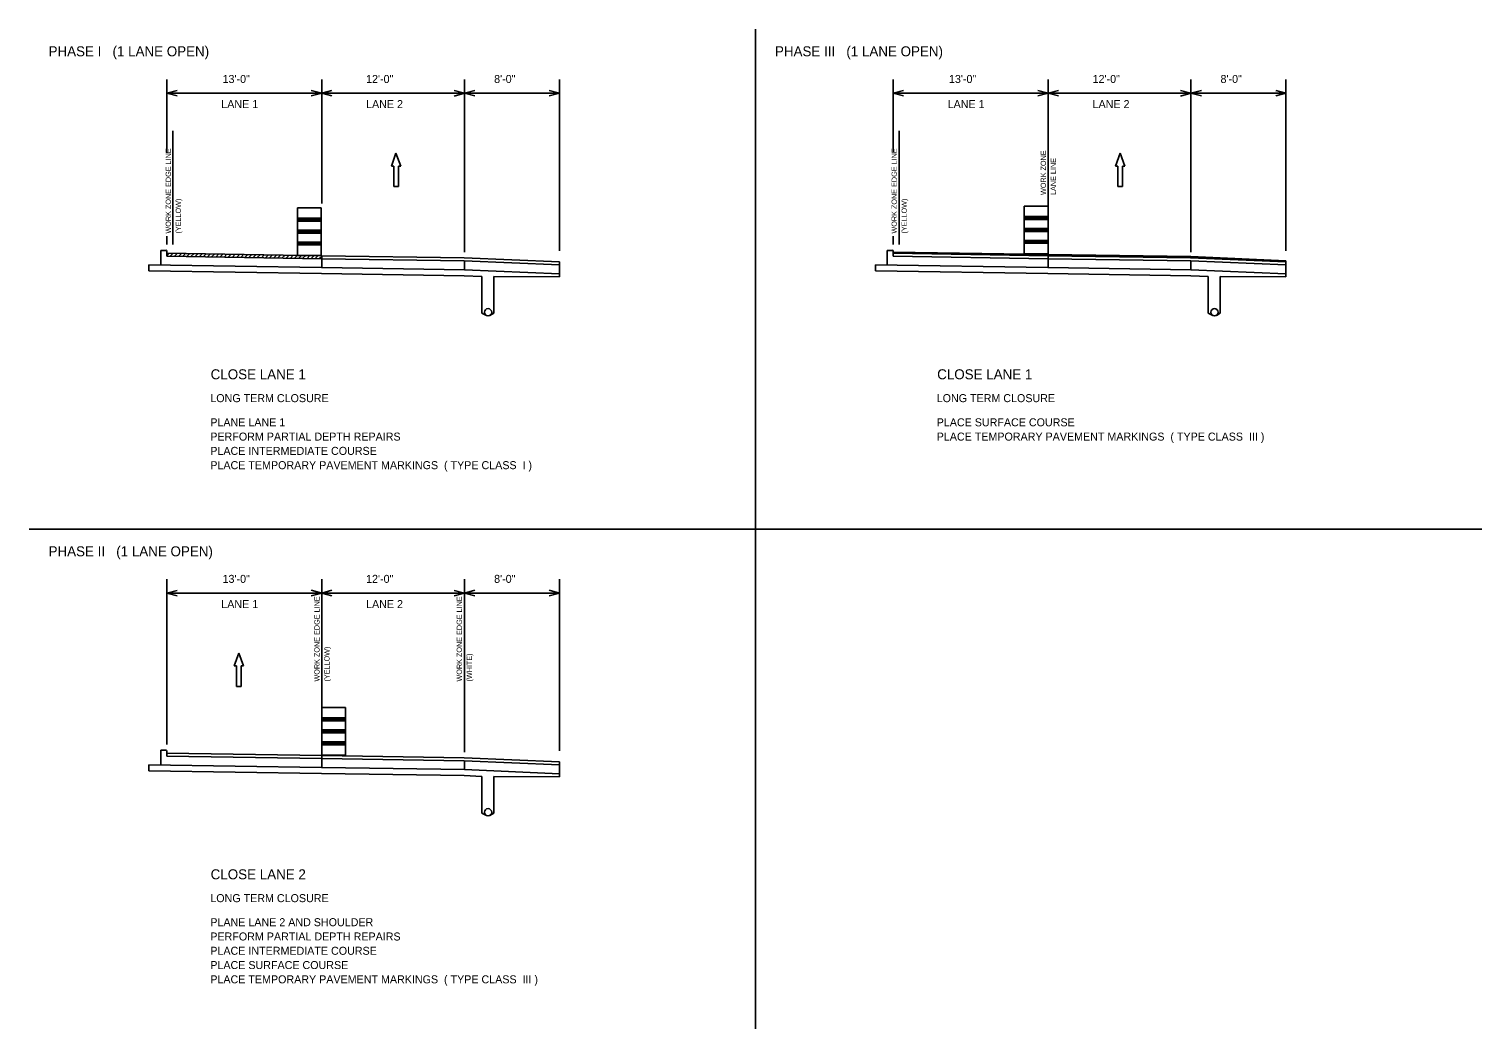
# Model space of a CAD drawing. Extents: x -161 to 291, y -369 to 173.
# Drawn here: x 169.5 to 291.5, y 2 to 86 of the extents above; entities that cross this region are included whole.
import ezdxf

# ---------------------------------------------------------------- set-up
doc = ezdxf.new("R2010")
doc.units = 0
for name, color, linetype in [('Level 1', 7, 'Continuous'), ('Level 11', 7, 'Continuous'), ('Level 21', 7, 'Continuous'), ('Level 25', 7, 'Continuous'), ('Level 26', 7, 'Continuous'), ('Level 6', 7, 'Continuous'), ('Level 7', 7, 'Continuous')]:
    doc.layers.add(name, color=color, linetype=linetype)

msp = doc.modelspace()

# ---------------------------------------------------------------- linework, layer by layer
at = {"layer": 'Level 1'}
for p, q in [((230.49, 44), (230.49, 86)), ((230.49, 44), (230.49, 86)), ((169.49, 44), (230.49, 44)), ((169.49, 44), (230.49, 44)), ((230.49, 2.01), (230.49, 44)), ((230.49, 44), (291.48, 44))]:
    msp.add_line(p, q, dxfattribs=at)
at = {"layer": 'Level 11'}
for p, q in [((180.56, 66.17), (180.56, 67.41)), ((180.56, 67.41), (180.97, 67.41)), ((181.06, 66.91), (181.06, 67.33)), ((194.06, 66.96), (181.06, 67.16)), ((181.06, 66.98), (181.24, 67.16)), ((181.34, 66.91), (181.58, 67.16)), ((181.69, 66.91), (181.93, 67.15)), ((182.03, 66.9), (182.28, 67.15)), ((182.38, 66.89), (182.63, 67.14)), ((182.73, 66.89), (182.98, 67.14)), ((183.08, 66.88), (183.33, 67.13)), ((183.43, 66.88), (183.67, 67.12)), ((183.78, 66.87), (184.02, 67.12)), ((184.12, 66.87), (184.37, 67.11)), ((184.47, 66.86), (184.72, 67.11)), ((184.82, 66.86), (185.07, 67.1)), ((185.17, 66.85), (185.41, 67.1)), ((241.55, 66.17), (241.55, 67.41)), ((241.55, 67.41), (241.97, 67.41)), ((242.05, 66.91), (242.05, 67.33)), ((194.04, 65.97), (179.56, 66.19)), ((179.56, 65.69), (179.56, 66.19)), ((194.06, 66.71), (181.06, 66.91)), ((185.52, 66.85), (185.76, 67.09)), ((185.86, 66.84), (186.11, 67.09)), ((186.21, 66.84), (186.46, 67.08)), ((186.56, 66.83), (186.81, 67.08)), ((186.91, 66.82), (187.16, 67.07)), ((187.26, 66.82), (187.5, 67.07)), ((187.61, 66.81), (187.85, 67.06)), ((187.95, 66.81), (188.2, 67.05)), ((188.3, 66.8), (188.55, 67.05)), ((188.65, 66.8), (188.9, 67.04)), ((189, 66.79), (189.24, 67.04)), ((189.35, 66.79), (189.59, 67.03)), ((189.69, 66.78), (189.94, 67.03)), ((190.04, 66.78), (190.29, 67.02)), ((190.39, 66.77), (190.64, 67.02)), ((190.74, 66.77), (190.99, 67.01)), ((191.09, 66.76), (191.33, 67.01)), ((191.44, 66.75), (191.68, 67)), ((191.78, 66.75), (192.03, 67)), ((192.13, 66.74), (192.38, 66.99)), ((192.48, 66.74), (192.73, 66.98)), ((192.83, 66.73), (193.07, 66.98)), ((193.18, 66.73), (193.42, 66.97)), ((193.52, 66.72), (193.77, 66.97)), ((193.87, 66.72), (194.06, 66.9)), ((194.06, 66.71), (194.06, 66.96)), ((206.03, 66.78), (194.06, 66.96)), ((206.03, 66.53), (194.06, 66.71)), ((194.06, 65.97), (194.06, 66.71)), ((206.05, 65.78), (194.06, 65.97)), ((214.03, 66.44), (206.03, 66.78)), ((214.03, 66.19), (206.03, 66.53)), ((206.06, 65.78), (206.06, 66.53)), ((214.03, 65.2), (214.03, 66.44)), ((255.04, 65.97), (240.55, 66.19)), ((240.55, 65.69), (240.55, 66.19)), ((255.05, 66.96), (255.05, 66.71)), ((255.05, 65.97), (255.05, 66.71)), ((267.04, 65.78), (255.05, 65.97)), ((267.05, 65.78), (267.05, 66.53)), ((275.02, 65.2), (275.02, 66.19)), ((194.04, 65.47), (179.56, 65.69)), ((206.03, 65.28), (194.04, 65.47)), ((207.5, 65.22), (206.03, 65.28)), ((214.03, 65.45), (206.05, 65.78)), ((207.51, 65.22), (207.51, 62.13)), ((208.51, 65.22), (208.51, 62.14)), ((214.03, 65.2), (208.51, 65.22)), ((255.03, 65.47), (240.55, 65.69)), ((267.03, 65.28), (255.04, 65.47)), ((268.5, 65.22), (267.03, 65.28)), ((275.02, 65.45), (267.04, 65.78)), ((268.5, 65.22), (268.5, 62.13)), ((269.5, 65.22), (269.5, 62.14)), ((275.02, 65.2), (269.5, 65.22)), ((207.9, 61.94), (207.51, 62.13)), ((208.19, 61.95), (208.51, 62.14)), ((268.89, 61.94), (268.5, 62.13)), ((269.18, 61.95), (269.5, 62.14)), ((180.56, 24.18), (180.56, 25.42)), ((180.56, 25.42), (180.97, 25.42)), ((181.06, 24.92), (181.06, 25.34)), ((206.03, 24.78), (194.06, 24.97)), ((194.06, 24.97), (194.06, 24.72)), ((194.06, 23.97), (194.06, 24.72)), ((194.06, 24.72), (206.03, 24.53)), ((214.03, 24.45), (206.03, 24.78)), ((206.03, 24.53), (214.03, 24.2)), ((206.06, 23.78), (206.06, 24.53)), ((214.03, 24.2), (214.03, 24.45)), ((194.04, 23.97), (179.56, 24.19)), ((179.56, 23.69), (179.56, 24.19)), ((194.04, 23.47), (179.56, 23.69)), ((206.03, 23.29), (194.04, 23.47)), ((206.05, 23.79), (194.06, 23.97)), ((207.5, 23.22), (206.03, 23.29)), ((214.03, 23.45), (206.05, 23.79)), ((207.51, 23.22), (207.51, 20.13)), ((208.51, 23.22), (208.51, 20.14)), ((214.03, 23.2), (208.51, 23.22)), ((214.03, 23.2), (214.03, 24.2)), ((207.9, 19.94), (207.51, 20.13)), ((208.19, 19.95), (208.51, 20.14))]:
    msp.add_line(p, q, dxfattribs=at)
for centre in [(208.03, 62.21), (269.02, 62.21), (208.03, 20.21)]:
    msp.add_circle(centre, 0.304, dxfattribs=at)
for centre in [(180.97, 67.33), (241.97, 67.33), (180.97, 25.34)]:
    msp.add_arc(centre, 0.083, 0, 90, dxfattribs=at)
at = {"layer": 'Level 21'}
for p, q in [((242.05, 67.26), (242.05, 66.91)), ((255.05, 67.06), (242.05, 67.26)), ((255.05, 66.96), (242.05, 67.16)), ((255.05, 66.71), (242.05, 66.91)), ((255.05, 66.71), (255.05, 66.96)), ((267.02, 66.78), (255.05, 66.96)), ((255.05, 66.71), (267.03, 66.53)), ((267.03, 66.88), (255.06, 67.06)), ((275.02, 66.44), (267.02, 66.78)), ((275.02, 66.54), (267.03, 66.88)), ((267.03, 66.53), (275.02, 66.19)), ((275.02, 66.19), (275.02, 66.54)), ((194.06, 24.97), (181.06, 25.17)), ((181.06, 25.17), (181.06, 24.92)), ((194.06, 24.72), (181.06, 24.92)), ((194.06, 24.72), (194.06, 24.97))]:
    msp.add_line(p, q, dxfattribs=at)
at = {"layer": 'Level 25'}
for p, q in [((192.03, 70.98), (192.03, 66.98)), ((192.03, 70.98), (194.03, 70.98)), ((194.03, 70.98), (194.03, 66.98)), ((253.05, 71.12), (253.05, 67.12)), ((253.05, 71.12), (255.05, 71.12)), ((255.05, 71.12), (255.05, 67.12)), ((192.03, 70.11), (194.03, 70.11)), ((192.03, 69.98), (194.03, 69.98)), ((192.03, 69.86), (194.03, 69.86)), ((253.05, 70.25), (255.05, 70.25)), ((253.05, 70.12), (255.05, 70.12)), ((253.05, 70), (255.05, 70)), ((192.03, 69.11), (194.03, 69.11)), ((192.03, 68.98), (194.03, 68.98)), ((192.03, 68.86), (194.03, 68.86)), ((253.05, 69.25), (255.05, 69.25)), ((253.05, 69.12), (255.05, 69.12)), ((253.05, 69), (255.05, 69)), ((192.03, 68.11), (194.03, 68.11)), ((192.03, 67.98), (194.03, 67.98)), ((192.03, 67.86), (194.03, 67.86)), ((253.05, 68.25), (255.05, 68.25)), ((253.05, 68.12), (255.05, 68.12)), ((253.05, 68), (255.05, 68)), ((253.05, 67.12), (255.05, 67.12)), ((192.03, 66.98), (194.03, 66.98)), ((194.06, 29.01), (194.06, 25.01)), ((194.06, 29.01), (196.06, 29.01)), ((194.06, 28.13), (196.06, 28.13)), ((196.06, 29.01), (196.06, 25.01)), ((194.06, 28.01), (196.06, 28.01)), ((194.06, 27.88), (196.06, 27.88)), ((194.06, 27.13), (196.06, 27.13)), ((194.06, 27.01), (196.06, 27.01)), ((194.06, 26.88), (196.06, 26.88)), ((194.06, 26.13), (196.06, 26.13)), ((194.06, 26.01), (196.06, 26.01)), ((194.06, 25.88), (196.06, 25.88)), ((194.06, 25.01), (196.06, 25.01))]:
    msp.add_line(p, q, dxfattribs=at)
at = {"layer": 'Level 26'}
for p, q in [((181.06, 75.61), (181.06, 81.77)), ((194.06, 71.35), (194.06, 81.77)), ((206.06, 67.26), (206.06, 81.77)), ((214.03, 67.36), (214.03, 81.77)), ((242.05, 75.62), (242.05, 81.77)), ((255.05, 67.13), (255.05, 81.77)), ((267.05, 67.26), (267.05, 81.77)), ((275.02, 67.36), (275.02, 81.77)), ((181.06, 80.61), (194.06, 80.61)), ((206.06, 80.61), (194.06, 80.61)), ((214.03, 80.61), (206.06, 80.61)), ((242.05, 80.61), (255.05, 80.61)), ((267.05, 80.61), (255.05, 80.61)), ((275.02, 80.61), (267.05, 80.61)), ((181.56, 67.89), (181.56, 77.45)), ((242.55, 67.89), (242.55, 77.45)), ((181.06, 67.89), (181.06, 68.61)), ((242.05, 67.89), (242.05, 68.61)), ((181.06, 26.61), (181.06, 39.78)), ((194.06, 25.13), (194.06, 39.78)), ((206.06, 25.26), (206.06, 39.78)), ((214.03, 25.37), (214.03, 39.78)), ((181.06, 38.62), (194.06, 38.62)), ((206.06, 38.62), (194.06, 38.62)), ((214.03, 38.62), (206.06, 38.62)), ((181.06, 25.9), (181.06, 26.61))]:
    msp.add_line(p, q, dxfattribs=at)
for points in [[(181.92, 80.38), (181.06, 80.61), (181.92, 80.85)], [(193.19, 80.85), (194.06, 80.61), (193.19, 80.38)], [(194.92, 80.85), (194.06, 80.61), (194.92, 80.38)], [(205.19, 80.37), (206.06, 80.61), (205.19, 80.85)], [(206.92, 80.85), (206.06, 80.61), (206.92, 80.38)], [(213.16, 80.85), (214.03, 80.61), (213.16, 80.38)], [(242.92, 80.38), (242.05, 80.61), (242.92, 80.85)], [(254.18, 80.85), (255.05, 80.61), (254.18, 80.38)], [(255.92, 80.85), (255.05, 80.61), (255.92, 80.38)], [(266.18, 80.37), (267.05, 80.61), (266.18, 80.85)], [(267.92, 80.85), (267.05, 80.61), (267.92, 80.38)], [(274.16, 80.85), (275.02, 80.61), (274.16, 80.38)], [(181.92, 38.38), (181.06, 38.62), (181.92, 38.85)], [(193.19, 38.86), (194.06, 38.62), (193.19, 38.39)], [(194.92, 38.86), (194.06, 38.62), (194.92, 38.39)], [(205.19, 38.38), (206.06, 38.62), (205.19, 38.85)], [(206.92, 38.86), (206.06, 38.62), (206.92, 38.39)], [(213.16, 38.86), (214.03, 38.62), (213.16, 38.39)]]:
    msp.add_lwpolyline(points, dxfattribs=at)
at = {"layer": 'Level 7'}
for p, q in [((200.3, 75.56), (199.91, 74.49)), ((199.91, 74.49), (200.11, 74.49)), ((200.11, 74.49), (200.11, 72.77)), ((200.71, 74.49), (200.3, 75.56)), ((200.5, 72.77), (200.5, 74.49)), ((200.5, 74.49), (200.71, 74.49)), ((261.1, 75.56), (260.7, 74.49)), ((260.7, 74.49), (260.91, 74.49)), ((260.91, 74.49), (260.91, 72.77)), ((261.5, 74.49), (261.1, 75.56)), ((261.3, 72.77), (261.3, 74.49)), ((261.3, 74.49), (261.5, 74.49)), ((200.11, 72.77), (200.5, 72.77)), ((260.91, 72.77), (261.3, 72.77)), ((187.11, 33.57), (186.71, 32.5)), ((187.51, 32.5), (187.11, 33.57)), ((186.71, 32.5), (186.91, 32.5)), ((186.91, 32.5), (186.91, 30.77)), ((187.3, 30.77), (187.3, 32.5)), ((187.3, 32.5), (187.51, 32.5)), ((186.91, 30.77), (187.3, 30.77))]:
    msp.add_line(p, q, dxfattribs=at)

# ---------------------------------------------------------------- texts
at = {"layer": 'Level 26'}
for s, p in [('13\'-0"', (185.74, 81.47)), ('12\'-0"', (197.79, 81.47)), ('8\'-0"', (208.54, 81.47)), ('13\'-0"', (246.73, 81.47)), ('12\'-0"', (258.79, 81.47)), ('8\'-0"', (269.53, 81.47)), ('LANE 1', (185.63, 79.36)), ('LANE 2', (197.79, 79.36)), ('LANE 1', (246.62, 79.36)), ('LANE 2', (258.79, 79.36)), ('13\'-0"', (185.74, 39.48)), ('12\'-0"', (197.79, 39.48)), ('8\'-0"', (208.54, 39.48)), ('LANE 1', (185.63, 37.36)), ('LANE 2', (197.79, 37.36))]:
    msp.add_text(s, height=0.672, dxfattribs=at).set_placement(p)
for s, p in [('WORK ZONE EDGE LINE', (181.4, 68.82)), ('WORK ZONE EDGE LINE', (242.35, 68.82)), ('WORK ZONE', (254.87, 72.06)), ('LANE LINE', (255.71, 72.06)), ('(YELLOW) ', (182.24, 68.82)), ('(YELLOW) ', (243.19, 68.82)), ('WORK ZONE EDGE LINE', (193.88, 31.19)), ('WORK ZONE EDGE LINE', (205.83, 31.19)), ('(YELLOW) ', (194.72, 31.19)), ('(WHITE) ', (206.67, 31.19))]:
    msp.add_text(s, height=0.44, rotation=90, dxfattribs=at).set_placement(p)
at = {"layer": 'Level 6'}
for s, height, p in [('PHASE I   (1 LANE OPEN)', 0.84, (171.13, 83.71)), ('PHASE III   (1 LANE OPEN)', 0.84, (232.12, 83.71)), ('CLOSE LANE 1', 0.84, (184.74, 56.58)), ('CLOSE LANE 1', 0.84, (245.74, 56.58)), ('LONG TERM CLOSURE', 0.672, (184.71, 54.66)), ('LONG TERM CLOSURE', 0.672, (245.7, 54.66)), ('PLANE LANE 1 ', 0.672, (184.71, 52.63)), ('PLACE SURFACE COURSE', 0.672, (245.7, 52.63)), ('PERFORM PARTIAL DEPTH REPAIRS', 0.672, (184.71, 51.43)), ('PLACE TEMPORARY PAVEMENT MARKINGS  ( TYPE CLASS  III )', 0.672, (245.7, 51.43)), ('PLACE INTERMEDIATE COURSE', 0.672, (184.71, 50.23)), ('PLACE TEMPORARY PAVEMENT MARKINGS  ( TYPE CLASS  I )', 0.672, (184.71, 49.03)), ('PHASE II   (1 LANE OPEN)', 0.84, (171.13, 41.71)), ('CLOSE LANE 2', 0.84, (184.74, 14.58)), ('LONG TERM CLOSURE', 0.672, (184.71, 12.66)), ('PLANE LANE 2 AND SHOULDER', 0.672, (184.71, 10.64)), ('PERFORM PARTIAL DEPTH REPAIRS', 0.672, (184.71, 9.44)), ('PLACE INTERMEDIATE COURSE', 0.672, (184.71, 8.24)), ('PLACE SURFACE COURSE', 0.672, (184.71, 7.04)), ('PLACE TEMPORARY PAVEMENT MARKINGS  ( TYPE CLASS  III )', 0.672, (184.71, 5.84))]:
    msp.add_text(s, height=height, dxfattribs=at).set_placement(p)

doc.saveas('drawing.dxf')
